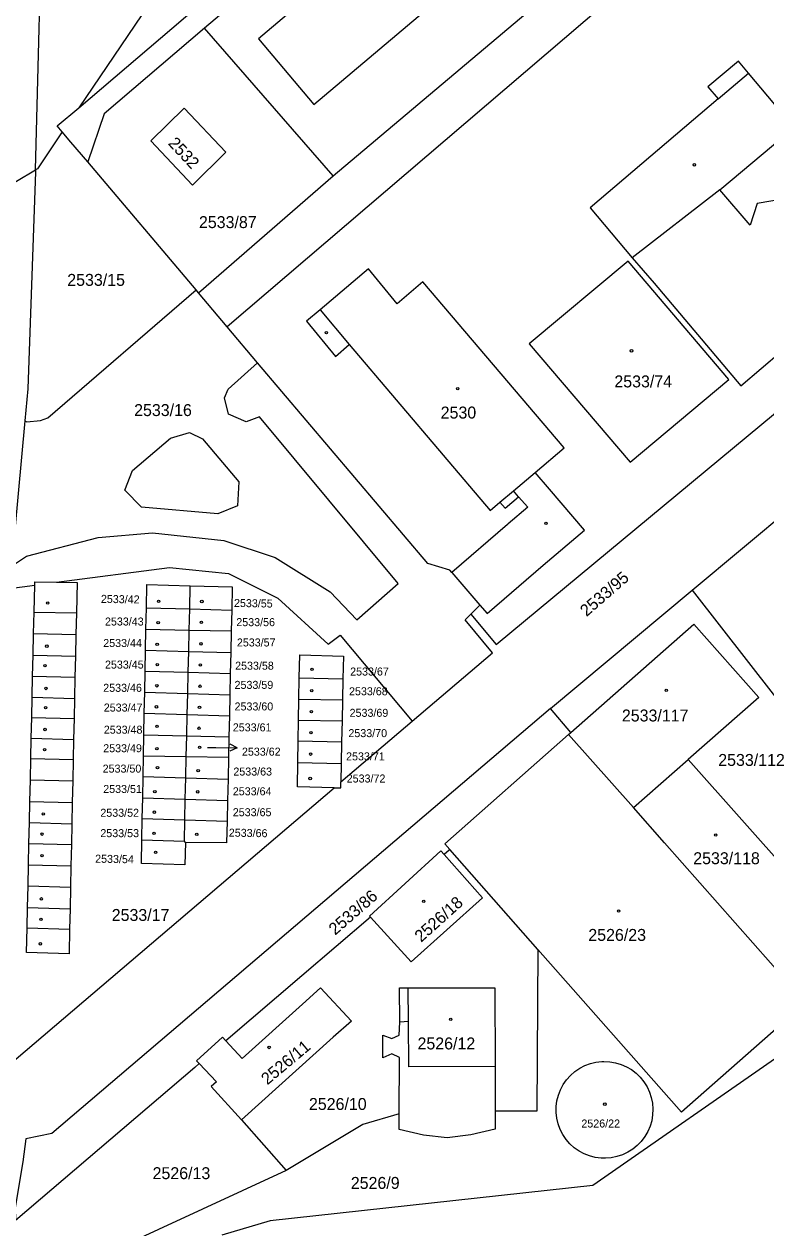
# Model space of a CAD drawing. Extents: x -527335 to -526256, y -1079142 to -1077836.
# Drawn here: x -527153 to -527047.3, y -1078353.8 to -1078182.5 of the extents above; entities that cross this region are included whole.
import ezdxf

# ---------------------------------------------------------------- set-up
doc = ezdxf.new("R2010")
doc.units = 0
for name, color, linetype in [('Hranice parcel', 7, 'Continuous'), ('Parcelní čísla', 7, 'Continuous'), ('Pop  PČ popisy', 7, 'Continuous'), ('Vnitřní kresba', 7, 'Continuous'), ('Značky budov', 7, 'Continuous')]:
    doc.layers.add(name, color=color, linetype=linetype)

msp = doc.modelspace()

# ---------------------------------------------------------------- linework, layer by layer
at = {"layer": 'Hranice parcel'}
for p, q in [((-527145.19, -1078194.36), (-527021.08, -1078088.59)), ((-527075.98, -1078139.33), (-527127.29, -1078183.04)), ((-527108.95, -1078204.05), (-527057.85, -1078160.95)), ((-527108.95, -1078204.05), (-527127.29, -1078183.04)), ((-527128.49, -1078220.29), (-527143.91, -1078202.08)), ((-527168.74, -1078213.47), (-527151.32, -1078203.19)), ((-527128.12, -1078220.72), (-527108.95, -1078204.05)), ((-527128.12, -1078220.72), (-527128.49, -1078220.29)), ((-527124.03, -1078225.56), (-527128.12, -1078220.72)), ((-527057.86, -1078263.05), (-527036.7, -1078245.38)), ((-527092.08, -1078260.53), (-527088.09, -1078265.17)), ((-527155.03, -1078262.79), (-527151.46, -1078262.32)), ((-527151.54, -1078266.16), (-527151.46, -1078262.32)), ((-527129.38, -1078265.72), (-527129.3, -1078262.42)), ((-527078.01, -1078279.88), (-527057.86, -1078263.05)), ((-527089.37, -1078266.47), (-527088.09, -1078265.17)), ((-527151.61, -1078269.21), (-527151.54, -1078266.16)), ((-527151.54, -1078266.16), (-527145.52, -1078266.29)), ((-527145.52, -1078266.29), (-527145.59, -1078269.35)), ((-527135.61, -1078268.58), (-527135.55, -1078265.55)), ((-527135.55, -1078265.55), (-527129.38, -1078265.72)), ((-527129.45, -1078268.72), (-527129.38, -1078265.72)), ((-527129.38, -1078265.72), (-527123.41, -1078265.88)), ((-527123.41, -1078265.88), (-527123.48, -1078268.86)), ((-527135.67, -1078271.6), (-527135.61, -1078268.58)), ((-527135.61, -1078268.58), (-527129.45, -1078268.72)), ((-527129.52, -1078271.76), (-527129.45, -1078268.72)), ((-527129.45, -1078268.72), (-527123.48, -1078268.86)), ((-527123.48, -1078268.86), (-527123.54, -1078271.91)), ((-527151.68, -1078272.29), (-527151.61, -1078269.21)), ((-527151.61, -1078269.21), (-527145.59, -1078269.35)), ((-527145.59, -1078269.35), (-527145.65, -1078272.43)), ((-527151.75, -1078275.29), (-527151.68, -1078272.29)), ((-527151.68, -1078272.29), (-527145.65, -1078272.43)), ((-527135.73, -1078274.57), (-527135.67, -1078271.6)), ((-527135.67, -1078271.6), (-527129.52, -1078271.76)), ((-527129.59, -1078274.74), (-527129.52, -1078271.76)), ((-527129.52, -1078271.76), (-527123.54, -1078271.91)), ((-527123.54, -1078271.91), (-527123.61, -1078274.91)), ((-527145.65, -1078272.43), (-527145.72, -1078275.44)), ((-527151.81, -1078278.3), (-527151.75, -1078275.29)), ((-527151.75, -1078275.29), (-527145.72, -1078275.44)), ((-527145.72, -1078275.44), (-527145.78, -1078278.45)), ((-527135.79, -1078277.57), (-527135.73, -1078274.57)), ((-527135.73, -1078274.57), (-527129.59, -1078274.74)), ((-527129.66, -1078277.76), (-527129.59, -1078274.74)), ((-527129.59, -1078274.74), (-527123.61, -1078274.91)), ((-527123.61, -1078274.91), (-527123.67, -1078277.94)), ((-527113.83, -1078278.55), (-527113.78, -1078275.52)), ((-527113.78, -1078275.52), (-527107.58, -1078275.66)), ((-527107.58, -1078275.66), (-527107.64, -1078278.68)), ((-527151.87, -1078281.17), (-527151.81, -1078278.3)), ((-527151.81, -1078278.3), (-527145.78, -1078278.45)), ((-527145.78, -1078278.45), (-527145.84, -1078281.32)), ((-527135.85, -1078280.57), (-527135.79, -1078277.57)), ((-527135.79, -1078277.57), (-527129.66, -1078277.76)), ((-527129.73, -1078280.76), (-527129.66, -1078277.76)), ((-527129.66, -1078277.76), (-527123.67, -1078277.94)), ((-527123.67, -1078277.94), (-527123.74, -1078280.95)), ((-527113.88, -1078281.54), (-527113.83, -1078278.55)), ((-527113.83, -1078278.55), (-527107.64, -1078278.68)), ((-527107.64, -1078278.68), (-527107.7, -1078281.67)), ((-527135.9, -1078283.62), (-527135.85, -1078280.57)), ((-527135.85, -1078280.57), (-527129.73, -1078280.76)), ((-527129.8, -1078283.77), (-527129.73, -1078280.76)), ((-527129.73, -1078280.76), (-527123.74, -1078280.95)), ((-527075.11, -1078283.3), (-527078.01, -1078279.88)), ((-527151.94, -1078284.13), (-527151.87, -1078281.17)), ((-527151.87, -1078281.17), (-527145.84, -1078281.32)), ((-527145.84, -1078281.32), (-527145.91, -1078284.29)), ((-527123.74, -1078280.95), (-527123.8, -1078283.92)), ((-527113.94, -1078284.52), (-527113.88, -1078281.54)), ((-527113.88, -1078281.54), (-527107.7, -1078281.67)), ((-527107.87, -1078290.35), (-527097.7, -1078281.69)), ((-527107.7, -1078281.67), (-527107.76, -1078284.66)), ((-527152, -1078287), (-527151.94, -1078284.13)), ((-527151.94, -1078284.13), (-527145.91, -1078284.29)), ((-527145.91, -1078284.29), (-527145.97, -1078287.16)), ((-527135.96, -1078286.61), (-527135.9, -1078283.62)), ((-527135.9, -1078283.62), (-527129.8, -1078283.77)), ((-527129.87, -1078286.72), (-527129.8, -1078283.77)), ((-527129.8, -1078283.77), (-527123.8, -1078283.92)), ((-527123.8, -1078283.92), (-527123.87, -1078286.82)), ((-527075.43, -1078283.58), (-527075.11, -1078283.3)), ((-527066.22, -1078294.01), (-527075.43, -1078283.58)), ((-527113.99, -1078287.59), (-527113.94, -1078284.52)), ((-527113.94, -1078284.52), (-527107.76, -1078284.66)), ((-527107.76, -1078284.66), (-527107.82, -1078287.72)), ((-527152.07, -1078290.04), (-527152, -1078287)), ((-527152, -1078287), (-527145.97, -1078287.16)), ((-527145.97, -1078287.16), (-527146.03, -1078290.2)), ((-527136.02, -1078289.59), (-527135.96, -1078286.61)), ((-527135.96, -1078286.61), (-527129.87, -1078286.72)), ((-527129.94, -1078289.78), (-527129.87, -1078286.72)), ((-527129.87, -1078286.72), (-527123.87, -1078286.82)), ((-527123.87, -1078286.82), (-527123.93, -1078289.96)), ((-527113.99, -1078287.59), (-527107.82, -1078287.72)), ((-527107.82, -1078287.72), (-527107.87, -1078290.35)), ((-527066.22, -1078294.01), (-527058.42, -1078287.16)), ((-527058.42, -1078287.16), (-527040.76, -1078307.03)), ((-527152.14, -1078293.13), (-527152.07, -1078290.04)), ((-527152.07, -1078290.04), (-527146.03, -1078290.2)), ((-527146.03, -1078290.2), (-527146.1, -1078293.3)), ((-527136.08, -1078292.63), (-527136.02, -1078289.59)), ((-527136.02, -1078289.59), (-527129.94, -1078289.78)), ((-527130.01, -1078292.81), (-527129.94, -1078289.78)), ((-527129.94, -1078289.78), (-527123.93, -1078289.96)), ((-527123.93, -1078289.96), (-527124, -1078292.98)), ((-527136.14, -1078295.56), (-527136.08, -1078292.63)), ((-527136.08, -1078292.63), (-527130.01, -1078292.81)), ((-527130.08, -1078295.75), (-527130.01, -1078292.81)), ((-527130.01, -1078292.81), (-527124, -1078292.98)), ((-527152.2, -1078296.14), (-527152.14, -1078293.13)), ((-527152.14, -1078293.13), (-527146.1, -1078293.3)), ((-527146.1, -1078293.3), (-527146.16, -1078296.31)), ((-527124, -1078292.98), (-527124.06, -1078295.93)), ((-527152.27, -1078299.1), (-527152.2, -1078296.14)), ((-527152.2, -1078296.14), (-527146.16, -1078296.31)), ((-527146.16, -1078296.31), (-527146.23, -1078299.27)), ((-527136.19, -1078298.58), (-527136.14, -1078295.56)), ((-527136.14, -1078295.56), (-527130.08, -1078295.75)), ((-527130.15, -1078298.8), (-527130.08, -1078295.75)), ((-527130.08, -1078295.75), (-527124.06, -1078295.93)), ((-527152.34, -1078302.13), (-527152.27, -1078299.1)), ((-527152.27, -1078299.1), (-527146.23, -1078299.27)), ((-527146.23, -1078299.27), (-527146.29, -1078302.31)), ((-527136.19, -1078298.58), (-527130.15, -1078298.8)), ((-527129.99, -1078298.98), (-527130.15, -1078298.8)), ((-527079.8, -1078314.2), (-527092.36, -1078299.98)), ((-527152.4, -1078305.13), (-527152.34, -1078302.13)), ((-527152.34, -1078302.13), (-527146.29, -1078302.31)), ((-527146.29, -1078302.31), (-527146.36, -1078305.31)), ((-527152.47, -1078308.23), (-527152.4, -1078305.13)), ((-527152.4, -1078305.13), (-527146.36, -1078305.31)), ((-527146.36, -1078305.31), (-527146.42, -1078308.41)), ((-527152.53, -1078311.13), (-527152.47, -1078308.23)), ((-527152.47, -1078308.23), (-527146.42, -1078308.41)), ((-527146.42, -1078308.41), (-527146.49, -1078311.32)), ((-527152.53, -1078311.13), (-527146.49, -1078311.32)), ((-527122.01, -1078338.44), (-527115.65, -1078345.65))]:
    msp.add_line(p, q, dxfattribs=at)
for points in [[(-527151.32, -1078203.19), (-527149.15, -1078119.04), (-527147.89, -1078077.9), (-527146.9, -1078035.16), (-527147.21, -1078003.19)], [(-527021.08, -1078088.59), (-527032.67, -1078087.91), (-527048.92, -1078102.61), (-527126.32, -1078166.52), (-527145.19, -1078194.36)], [(-526994.58, -1078193.61), (-526995.55, -1078180.16), (-527023.46, -1078146.11), (-527026.79, -1078144.7), (-527030.6, -1078145.62), (-527124.03, -1078225.56)], [(-527073.25, -1078145.36), (-527119.6, -1078184.54), (-527111.69, -1078193.91), (-527065.33, -1078154.73), (-527073.25, -1078145.36)], [(-527127.29, -1078183.04), (-527141.57, -1078195.21), (-527143.91, -1078202.08)], [(-527044.98, -1078207.4), (-527048.61, -1078208), (-527049.6, -1078211.09), (-527053.92, -1078206.07), (-527043.32, -1078197.16), (-527049.81, -1078189.45), (-527051.27, -1078187.72), (-527055.6, -1078191.37), (-527054.14, -1078193.1), (-527072.36, -1078208.61), (-527066.4, -1078215.71), (-527063.27, -1078219.32), (-527050.92, -1078233.97), (-527045.12, -1078229.03)], [(-527147.53, -1078197.81), (-527148.24, -1078196.96), (-527145.19, -1078194.36)], [(-527130.16, -1078194.44), (-527134.92, -1078199.06), (-527128.97, -1078205.37), (-527124.24, -1078200.67), (-527130.16, -1078194.44)], [(-527147.53, -1078197.81), (-527151.07, -1078203.04), (-527151.32, -1078203.19)], [(-527143.91, -1078202.08), (-527146.31, -1078199.25), (-527147.53, -1078197.81)], [(-527151.32, -1078203.19), (-527151.33, -1078203.5), (-527152.45, -1078234.37), (-527152.87, -1078238.94)], [(-527088.09, -1078265.17), (-527087.05, -1078266.38), (-527079.07, -1078259.48), (-527073.18, -1078254.52), (-527078.17, -1078248.69), (-527080.22, -1078246.3), (-527076.09, -1078242.8), (-527096.17, -1078219.13), (-527099.86, -1078222.26), (-527103.94, -1078217.32), (-527110.79, -1078223.12), (-527112.74, -1078224.77), (-527108.62, -1078229.78), (-527106.7, -1078228.08), (-527086.6, -1078251.71), (-527085.21, -1078250.53), (-527084.47, -1078251.37), (-527082.56, -1078249.74), (-527081.22, -1078251.23), (-527084.03, -1078253.58), (-527084.16, -1078253.69), (-527092.08, -1078260.53)], [(-527066.97, -1078216.19), (-527081.03, -1078227.97), (-527066.68, -1078244.84), (-527052.61, -1078233.06), (-527066.97, -1078216.19)], [(-527152.87, -1078238.94), (-527152.57, -1078239.08), (-527150.64, -1078238.89), (-527149.6, -1078238.5), (-527128.49, -1078220.29)], [(-527092.08, -1078260.53), (-527092.34, -1078260.22), (-527095.48, -1078259.26), (-527119.71, -1078230.66), (-527124.03, -1078225.56)], [(-527089.37, -1078266.47), (-527085.73, -1078270.77), (-527044.03, -1078236.19)], [(-527152.87, -1078238.94), (-527154.74, -1078259.62), (-527154.85, -1078260.85)], [(-527148.36, -1078261.92), (-527132.28, -1078259.83), (-527123.87, -1078260.69), (-527116.82, -1078264.18), (-527109.65, -1078270.74), (-527107.97, -1078269.47), (-527097.7, -1078281.69)], [(-527151.46, -1078262.32), (-527151.45, -1078261.88), (-527148.36, -1078261.92)], [(-527148.36, -1078261.92), (-527145.43, -1078261.96), (-527145.52, -1078266.29)], [(-527135.55, -1078265.55), (-527135.49, -1078262.25), (-527129.3, -1078262.42)], [(-527129.3, -1078262.42), (-527123.34, -1078262.59), (-527123.41, -1078265.88)], [(-527057.86, -1078263.05), (-527045.96, -1078278.29), (-527030.55, -1078298.24)], [(-527097.7, -1078281.69), (-527086.26, -1078271.99), (-527090.15, -1078267.26), (-527089.37, -1078266.47)], [(-527075.11, -1078283.3), (-527057.6, -1078267.89), (-527048.34, -1078278.31), (-527058.42, -1078287.16)], [(-527113.78, -1078275.52), (-527113.72, -1078272.27), (-527107.51, -1078272.43), (-527107.58, -1078275.66)], [(-527078.01, -1078279.88), (-527149.04, -1078340.4), (-527152.71, -1078341.14), (-527153.16, -1078344.42), (-527154.22, -1078350.96), (-527154.21, -1078352.81)], [(-527092.36, -1078299.98), (-527093.08, -1078299.16), (-527075.43, -1078283.58)], [(-527108.84, -1078291.17), (-527114.05, -1078291.06), (-527113.99, -1078287.59)], [(-527157.99, -1078333.04), (-527157.02, -1078332.22), (-527108.84, -1078291.17)], [(-527108.84, -1078291.17), (-527107.89, -1078291.19), (-527107.87, -1078290.35)], [(-527041.68, -1078321.81), (-527061.79, -1078299.03), (-527066.22, -1078294.01)], [(-527124.06, -1078295.93), (-527124.13, -1078299.02), (-527129.99, -1078298.98)], [(-527129.99, -1078298.98), (-527130.08, -1078302.17), (-527136.26, -1078301.98), (-527136.19, -1078298.58)], [(-527093.17, -1078300.67), (-527093.64, -1078300.14), (-527103.79, -1078309.46), (-527103.65, -1078309.62)], [(-527093.17, -1078300.67), (-527087.7, -1078306.87), (-527097.86, -1078315.97), (-527103.65, -1078309.62)], [(-527092.36, -1078299.98), (-527092.46, -1078300.07), (-527093.17, -1078300.67)], [(-527103.65, -1078309.62), (-527113.42, -1078317.97), (-527124.23, -1078327.2)], [(-527146.49, -1078311.32), (-527146.56, -1078314.81), (-527152.61, -1078314.62), (-527152.53, -1078311.13)], [(-527079.8, -1078314.2), (-527079.96, -1078337.22), (-527085.89, -1078337.2)], [(-527045.51, -1078325.18), (-527059.35, -1078337.37), (-527079.8, -1078314.2)], [(-527124.23, -1078327.2), (-527121.9, -1078329.73), (-527113.33, -1078321.98), (-527110.74, -1078319.66), (-527106.36, -1078324.4), (-527108.94, -1078326.67), (-527122.01, -1078338.44)], [(-527099.54, -1078337.61), (-527099.52, -1078329.56), (-527100.62, -1078329.07), (-527101.88, -1078329.62), (-527101.91, -1078326.41), (-527100.61, -1078326.9), (-527099.56, -1078326.39), (-527099.48, -1078324.53), (-527099.52, -1078319.67), (-527098.29, -1078319.65), (-527085.93, -1078319.65), (-527085.9, -1078330.84), (-527085.89, -1078337.2)], [(-527045.51, -1078325.18), (-527044.42, -1078328.61), (-527072.01, -1078347.8), (-527117.91, -1078352.84), (-527124.8, -1078354.88)], [(-527124.23, -1078327.2), (-527124.71, -1078326.68), (-527128.43, -1078330.04), (-527128.03, -1078330.45)], [(-527128.03, -1078330.45), (-527128.68, -1078331), (-527154.21, -1078352.81)], [(-527128.03, -1078330.45), (-527125.55, -1078333.03), (-527126.31, -1078333.71), (-527122.01, -1078338.44)], [(-527063.47, -1078337.76), (-527063.61, -1078338.58), (-527063.84, -1078339.38), (-527064.17, -1078340.14), (-527064.59, -1078340.85), (-527065.09, -1078341.52), (-527065.66, -1078342.11), (-527066.31, -1078342.64), (-527067.01, -1078343.08), (-527067.76, -1078343.44), (-527068.55, -1078343.7), (-527069.36, -1078343.86), (-527070.19, -1078343.93), (-527070.82, -1078343.91), (-527071.64, -1078343.8), (-527072.45, -1078343.59), (-527073.22, -1078343.29), (-527073.95, -1078342.9), (-527074.63, -1078342.42), (-527075.24, -1078341.86), (-527075.79, -1078341.24), (-527076.25, -1078340.55), (-527076.63, -1078339.81), (-527076.92, -1078339.03), (-527077.11, -1078338.23), (-527077.21, -1078337.4), (-527077.2, -1078336.57), (-527077.09, -1078335.75), (-527076.89, -1078334.94), (-527076.59, -1078334.17), (-527076.2, -1078333.44), (-527075.72, -1078332.76), (-527075.17, -1078332.14), (-527074.55, -1078331.59), (-527073.86, -1078331.12), (-527073.12, -1078330.74), (-527072.34, -1078330.45), (-527071.54, -1078330.25), (-527070.71, -1078330.16), (-527070.4, -1078330.15), (-527069.57, -1078330.19), (-527068.76, -1078330.33), (-527067.96, -1078330.56), (-527067.2, -1078330.89), (-527066.48, -1078331.31), (-527065.82, -1078331.82), (-527065.23, -1078332.4), (-527064.71, -1078333.04), (-527064.27, -1078333.75), (-527063.92, -1078334.5), (-527063.66, -1078335.29), (-527063.5, -1078336.1), (-527063.43, -1078336.93), (-527063.47, -1078337.76)], [(-527085.89, -1078337.2), (-527085.89, -1078339.79), (-527089.34, -1078340.6), (-527092.71, -1078341), (-527096.09, -1078340.63), (-527099.54, -1078339.83), (-527099.54, -1078337.61)], [(-527099.54, -1078337.61), (-527104.73, -1078339.12), (-527115.65, -1078345.65)], [(-527115.65, -1078345.65), (-527152.02, -1078362.49), (-527154.6, -1078363.69)]]:
    msp.add_lwpolyline(points, dxfattribs=at)
at = {"layer": 'Pop  PČ popisy'}
for p, q in [((-527126.83, -1078285.43), (-527125.65, -1078285.45)), ((-527125.65, -1078285.45), (-527122.65, -1078285.5)), ((-527122.65, -1078285.5), (-527123.66, -1078285.99)), ((-527122.65, -1078285.5), (-527123.64, -1078284.98))]:
    msp.add_line(p, q, dxfattribs=at)
at = {"layer": 'Vnitřní kresba'}
for p, q in [((-527054.14, -1078193.1), (-527049.81, -1078189.45)), ((-527053.92, -1078206.07), (-527066.4, -1078215.71)), ((-527110.79, -1078223.12), (-527106.7, -1078228.08)), ((-527123.89, -1078234.43), (-527119.71, -1078230.66)), ((-527124.43, -1078235.67), (-527123.89, -1078234.43)), ((-527123.84, -1078237.98), (-527124.43, -1078235.67)), ((-527121.35, -1078239.1), (-527123.84, -1078237.98)), ((-527119.46, -1078238.39), (-527121.35, -1078239.1)), ((-527099.7, -1078262.11), (-527119.46, -1078238.39)), ((-527137.51, -1078246.01), (-527132.14, -1078241.43)), ((-527132.14, -1078241.43), (-527129.43, -1078240.6)), ((-527129.43, -1078240.6), (-527127.57, -1078241.48)), ((-527127.57, -1078241.48), (-527122.37, -1078247.62)), ((-527138.63, -1078248.82), (-527137.51, -1078246.01)), ((-527083.3, -1078248.91), (-527080.22, -1078246.3)), ((-527122.37, -1078247.62), (-527122.57, -1078251.03)), ((-527136.23, -1078251.24), (-527138.63, -1078248.82)), ((-527085.21, -1078250.53), (-527083.3, -1078248.91)), ((-527082.56, -1078249.74), (-527083.3, -1078248.91)), ((-527125.36, -1078252.17), (-527136.23, -1078251.24)), ((-527122.57, -1078251.03), (-527125.36, -1078252.17)), ((-527142.42, -1078255.53), (-527134.69, -1078254.87)), ((-527134.69, -1078254.87), (-527124.53, -1078255.97)), ((-527152.61, -1078258.22), (-527142.42, -1078255.53)), ((-527124.53, -1078255.97), (-527117.21, -1078258.41)), ((-527154.74, -1078259.62), (-527152.61, -1078258.22)), ((-527117.21, -1078258.41), (-527109.4, -1078263.29)), ((-527109.4, -1078263.29), (-527105.58, -1078267.28)), ((-527105.58, -1078267.28), (-527099.7, -1078262.11)), ((-527098.24, -1078324.47), (-527098.29, -1078319.65)), ((-527098.24, -1078324.47), (-527099.48, -1078324.53)), ((-527098.18, -1078330.92), (-527098.24, -1078324.47)), ((-527085.9, -1078330.84), (-527098.18, -1078330.92))]:
    msp.add_line(p, q, dxfattribs=at)
at = {"layer": 'Značky budov'}
for centre in [(-527057.53, -1078202.49), (-527109.92, -1078226.39), (-527066.48, -1078228.97), (-527091.23, -1078234.36), (-527078.67, -1078253.54), (-527149.6, -1078264.88), (-527133.82, -1078264.64), (-527127.66, -1078264.66), (-527133.88, -1078267.67), (-527127.73, -1078267.64), (-527134.02, -1078270.76), (-527127.79, -1078270.69), (-527149.73, -1078271.02), (-527150, -1078273.79), (-527134, -1078273.66), (-527127.86, -1078273.69), (-527111.96, -1078274.32), (-527149.86, -1078277.04), (-527134.06, -1078276.66), (-527127.92, -1078276.72), (-527112.01, -1078277.35), (-527061.53, -1078277.32), (-527149.91, -1078279.79), (-527134.12, -1078279.66), (-527127.99, -1078279.73), (-527112.06, -1078280.34), (-527134.04, -1078282.44), (-527128.05, -1078282.7), (-527149.99, -1078282.88), (-527112.12, -1078283.32), (-527150.05, -1078285.75), (-527134.06, -1078285.6), (-527127.98, -1078285.41), (-527112.17, -1078286.39), (-527133.97, -1078288.33), (-527128.18, -1078288.74), (-527112.23, -1078289.86), (-527134.35, -1078291.72), (-527128.25, -1078291.76), (-527134.41, -1078294.65), (-527150.24, -1078294.9), (-527150.41, -1078297.78), (-527134.46, -1078297.67), (-527128.38, -1078297.8), (-527054.49, -1078297.91), (-527150.41, -1078300.84), (-527134.24, -1078300.36), (-527150.5, -1078307), (-527096.06, -1078307.34), (-527150.57, -1078309.91), (-527068.32, -1078308.73), (-527150.64, -1078313.4), (-527092.22, -1078324.15), (-527118.08, -1078328.15), (-527070.28, -1078336.23)]:
    msp.add_circle(centre, 0.175, dxfattribs=at)

# ---------------------------------------------------------------- texts
at = {"layer": 'Parcelní čísla'}
for s, height, rotation, p in [('2532', 1.7, 313, (-527132.56, -1078199.51)), ('2533/95', 1.7, 41, (-527072.89, -1078266.9)), ('2533/42', 1.14, 359, (-527142.04, -1078264.85)), ('2533/42', 1.14, 359, (-527142.04, -1078264.85)), ('2533/55', 1.14, 359, (-527123.09, -1078265.43)), ('2533/55', 1.14, 359, (-527123.09, -1078265.43)), ('2533/66', 1.14, 359, (-527123.83, -1078298.13)), ('2533/66', 1.14, 359, (-527123.83, -1078298.13)), ('2533/54', 1.14, 359, (-527142.86, -1078301.84)), ('2533/86', 1.7, 41, (-527108.68, -1078312.24)), ('2526/18', 1.7, 42, (-527096.43, -1078313.25)), ('2526/11', 1.7, 40, (-527118.33, -1078333.56))]:
    msp.add_text(s, height=height, rotation=rotation, dxfattribs=at).set_placement(p)
for s, height, p in [('2533/87', 1.7, (-527128.07, -1078211.5)), ('2533/15', 1.7, (-527146.82, -1078219.72)), ('2533/74', 1.7, (-527068.92, -1078234.18)), ('2533/16', 1.7, (-527137.3, -1078238.26)), ('2530', 1.7, (-527093.65, -1078238.61)), ('2533/43', 1.139, (-527141.45, -1078268.08)), ('2533/43', 1.139, (-527141.45, -1078268.08)), ('2533/56', 1.139, (-527122.75, -1078268.17)), ('2533/56', 1.139, (-527122.75, -1078268.17)), ('2533/44', 1.139, (-527141.7, -1078271.14)), ('2533/44', 1.139, (-527141.7, -1078271.14)), ('2533/57', 1.139, (-527122.67, -1078271.06)), ('2533/57', 1.139, (-527122.67, -1078271.06)), ('2533/45', 1.139, (-527141.45, -1078274.21)), ('2533/45', 1.139, (-527141.45, -1078274.21)), ('2533/58', 1.139, (-527122.92, -1078274.37)), ('2533/58', 1.139, (-527122.92, -1078274.37)), ('2533/67', 1.139, (-527106.54, -1078275.2)), ('2533/67', 1.139, (-527106.54, -1078275.2)), ('2533/46', 1.139, (-527141.7, -1078277.52)), ('2533/46', 1.139, (-527141.7, -1078277.52)), ('2533/59', 1.139, (-527123, -1078277.1)), ('2533/59', 1.139, (-527123, -1078277.1)), ('2533/68', 1.139, (-527106.7, -1078278.01)), ('2533/68', 1.139, (-527106.7, -1078278.01)), ('2533/47', 1.139, (-527141.62, -1078280.33)), ('2533/47', 1.139, (-527141.62, -1078280.33)), ('2533/60', 1.139, (-527123, -1078280.17)), ('2533/60', 1.139, (-527123, -1078280.17)), ('2533/69', 1.139, (-527106.62, -1078281.08)), ('2533/69', 1.139, (-527106.62, -1078281.08)), ('2533/117', 1.7, (-527067.85, -1078281.74)), ('2533/48', 1.139, (-527141.62, -1078283.48)), ('2533/48', 1.139, (-527141.62, -1078283.48)), ('2533/61', 1.139, (-527123.25, -1078283.15)), ('2533/61', 1.139, (-527123.25, -1078283.15)), ('2533/70', 1.139, (-527106.79, -1078283.97)), ('2533/70', 1.139, (-527106.79, -1078283.97)), ('2533/49', 1.139, (-527141.7, -1078286.12)), ('2533/49', 1.139, (-527141.7, -1078286.12)), ('2533/62', 1.139, (-527121.95, -1078286.61)), ('2533/71', 1.139, (-527107.12, -1078287.28)), ('2533/71', 1.139, (-527107.12, -1078287.28)), ('2533/112', 1.7, (-527054.13, -1078288.07)), ('2533/50', 1.139, (-527141.78, -1078289.02)), ('2533/50', 1.139, (-527141.78, -1078289.02)), ('2533/63', 1.139, (-527123.17, -1078289.44)), ('2533/63', 1.139, (-527123.17, -1078289.44)), ('2533/72', 1.139, (-527107.03, -1078290.43)), ('2533/72', 1.139, (-527107.03, -1078290.43)), ('2533/51', 1.139, (-527141.7, -1078291.92)), ('2533/51', 1.139, (-527141.7, -1078291.92)), ('2533/64', 1.139, (-527123.25, -1078292.25)), ('2533/64', 1.139, (-527123.25, -1078292.25)), ('2533/52', 1.139, (-527142.11, -1078295.31)), ('2533/52', 1.139, (-527142.11, -1078295.31)), ('2533/65', 1.139, (-527123.25, -1078295.23)), ('2533/65', 1.139, (-527123.25, -1078295.23)), ('2533/53', 1.139, (-527142.11, -1078298.21)), ('2533/53', 1.139, (-527142.11, -1078298.21)), ('2533/118', 1.7, (-527057.69, -1078302.06)), ('2533/17', 1.7, (-527140.49, -1078310.14)), ('2526/23', 1.7, (-527072.63, -1078312.98)), ('2526/12', 1.7, (-527096.95, -1078328.43)), ('2526/10', 1.7, (-527112.41, -1078337.05)), ('2526/22', 1.14, (-527073.62, -1078339.55)), ('2526/13', 1.7, (-527134.67, -1078346.9)), ('2526/9', 1.7, (-527106.45, -1078348.29))]:
    msp.add_text(s, height=height, dxfattribs=at).set_placement(p)

doc.saveas('drawing.dxf')
